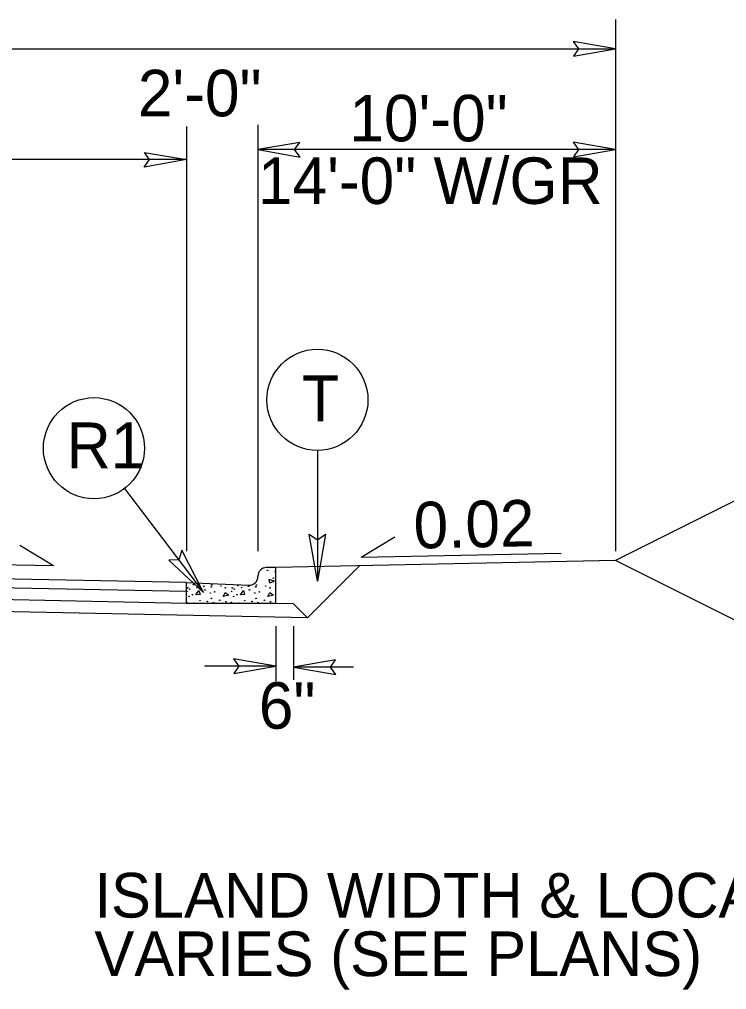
# Model space of a CAD drawing. Extents: x 1904401 to 1905163, y 193929 to 194736.
# Drawn here: x 1904998.98 to 1905018.76, y 194525.67 to 194552.8 of the extents above; entities that cross this region are included whole.
import ezdxf

# ---------------------------------------------------------------- set-up
doc = ezdxf.new("R2010")
doc.units = 0
for name, color, linetype in [('Default', 7, 'Continuous'), ('Old_Level_1', 7, 'Continuous'), ('Old_Level_11', 7, 'Continuous'), ('Old_Level_20', 7, 'Continuous'), ('Prop Dimension Text', 7, 'Continuous'), ('Prop Lane Arrow CELL', 7, 'Continuous'), ('Typical Arrow Superelevation CELL', 7, 'Continuous'), ('Typical Berm CELL', 7, 'Continuous'), ('Typical Curb CELL', 7, 'Continuous'), ('Typical Hinge Slope Arterial CELL', 7, 'Continuous'), ('Typical Pavement Slope CELL', 7, 'Continuous'), ('Typical Terminator CELL', 7, 'Continuous')]:
    doc.layers.add(name, color=color, linetype=linetype)

msp = doc.modelspace()

# ---------------------------------------------------------------- linework, layer by layer
at = {"layer": 'Default'}
msp.add_line((1905003.649, 194549.808), (1905003.649, 194537.934), dxfattribs=at)
at = {"layer": 'Old_Level_1'}
for p, q in [((1904952.149, 194551.972), (1905015.649, 194551.972)), ((1905015.649, 194549.16), (1905005.649, 194549.16)), ((1905003.649, 194548.88), (1904991.649, 194548.88))]:
    msp.add_line(p, q, dxfattribs=at)
at = {"layer": 'Old_Level_11'}
for p, q in [((1905007.314, 194540.747), (1905007.314, 194537.093)), ((1905001.92, 194539.682), (1905004.132, 194536.773))]:
    msp.add_line(p, q, dxfattribs=at)
for points in [[(1905007.54, 194538.402), (1905007.314, 194537.093), (1905007.081, 194538.409), (1905007.314, 194538.242)], [(1905003.16, 194537.679), (1905004.132, 194536.773), (1905003.521, 194537.962), (1905003.437, 194537.688)]]:
    msp.add_lwpolyline(points, close=True, dxfattribs=at)
for centre in [(1905007.314, 194542.161), (1905001.064, 194540.808)]:
    msp.add_circle(centre, 1.414, dxfattribs=at)
at = {"layer": 'Prop Dimension Text'}
for p, q in [((1905015.649, 194552.799), (1905015.649, 194537.934)), ((1905005.649, 194549.853), (1905005.649, 194537.934)), ((1905002.899, 194548.88), (1904991.899, 194548.88))]:
    msp.add_line(p, q, dxfattribs=at)
at = {"layer": 'Prop Lane Arrow CELL'}
for p, q in [((1905006.149, 194535.829), (1905006.149, 194534.291)), ((1905006.649, 194535.829), (1905006.649, 194534.331)), ((1905006.149, 194534.712), (1905004.159, 194534.712)), ((1905008.32, 194534.685), (1905006.649, 194534.685))]:
    msp.add_line(p, q, dxfattribs=at)
at = {"layer": 'Typical Arrow Superelevation CELL'}
for p, q in [((1904999.935, 194537.518), (1904998.995, 194538.086)), ((1905008.543, 194537.765), (1905009.483, 194538.333)), ((1905008.543, 194537.765), (1905014.136, 194537.876)), ((1904999.935, 194537.518), (1904994.864, 194537.619))]:
    msp.add_line(p, q, dxfattribs=at)
at = {"layer": 'Typical Berm CELL'}
msp.add_line((1905015.649, 194537.668), (1905006.149, 194537.47), dxfattribs=at)
at = {"layer": 'Typical Curb CELL'}
for p, q in [((1905006.149, 194537.47), (1905005.889, 194537.47)), ((1905006.149, 194536.47), (1905006.149, 194537.47)), ((1905003.649, 194536.47), (1905003.649, 194537.053)), ((1905003.649, 194537.053), (1905005.4, 194536.98)), ((1905005.649, 194537.22), (1905005.649, 194537.23)), ((1905005.958, 194537.137), (1905005.975, 194537.046)), ((1905006.113, 194537.092), (1905005.958, 194537.137)), ((1905005.975, 194537.046), (1905006.113, 194537.092)), ((1905003.91, 194536.71), (1905003.996, 194536.829)), ((1905004.031, 194536.716), (1905003.91, 194536.71)), ((1905003.996, 194536.829), (1905004.031, 194536.716)), ((1905004.675, 194536.659), (1905004.738, 194536.773)), ((1905004.738, 194536.773), (1905004.841, 194536.698)), ((1905005.16, 194536.71), (1905005.245, 194536.829)), ((1905005.279, 194536.716), (1905005.16, 194536.71)), ((1905005.245, 194536.829), (1905005.279, 194536.716)), ((1905005.924, 194536.659), (1905005.987, 194536.773)), ((1905005.987, 194536.773), (1905006.09, 194536.698)), ((1905006.149, 194536.47), (1905003.649, 194536.47)), ((1905004.841, 194536.698), (1905004.675, 194536.659)), ((1905006.09, 194536.698), (1905005.924, 194536.659))]:
    msp.add_line(p, q, dxfattribs=at)
for centre in [(1905005.919, 194537.394), (1905006.136, 194537.36), (1905003.848, 194536.995), (1905003.99, 194537.012), (1905004.361, 194536.983), (1905005.61, 194536.983), (1905006.084, 194537.177), (1905003.666, 194536.807), (1905003.683, 194536.904), (1905003.739, 194536.87), (1905003.819, 194536.71), (1905003.945, 194536.91), (1905004.139, 194536.949), (1905004.167, 194536.847), (1905004.316, 194536.761), (1905004.344, 194536.933), (1905004.441, 194536.79), (1905004.618, 194536.955), (1905004.738, 194536.904), (1905004.915, 194536.807), (1905004.932, 194536.904), (1905004.988, 194536.87), (1905005.068, 194536.71), (1905005.097, 194536.964), (1905005.194, 194536.91), (1905005.388, 194536.949), (1905005.416, 194536.847), (1905005.565, 194536.761), (1905005.593, 194536.933), (1905005.69, 194536.79), (1905005.867, 194536.955), (1905005.987, 194536.904), (1905003.66, 194536.499), (1905003.723, 194536.664), (1905003.871, 194536.476), (1905004.03, 194536.545), (1905004.236, 194536.522), (1905004.35, 194536.607), (1905004.407, 194536.493), (1905004.584, 194536.556), (1905004.755, 194536.516), (1905004.909, 194536.499), (1905004.972, 194536.664), (1905005.12, 194536.476), (1905005.279, 194536.545), (1905005.485, 194536.522), (1905005.599, 194536.607), (1905005.656, 194536.493), (1905005.833, 194536.556), (1905006.004, 194536.516)]:
    msp.add_circle(centre, 0.00802, dxfattribs=at)
for centre, start, end in [((1905005.889, 194537.23), 90, 180), ((1905005.41, 194537.22), 267.6155, 0)]:
    msp.add_arc(centre, 0.24, start, end, dxfattribs=at)
at = {"layer": 'Typical Hinge Slope Arterial CELL'}
for p in [(1905028.169, 194543.928), (1905028.102, 194531.442)]:
    msp.add_line(p, (1905015.649, 194537.668), dxfattribs=at)
at = {"layer": 'Typical Pavement Slope CELL'}
for p, q in [((1905003.649, 194537.053), (1904991.899, 194537.288)), ((1905007.04, 194536.069), (1905008.49, 194537.519)), ((1905003.649, 194536.803), (1904991.894, 194537.038)), ((1905007.04, 194536.069), (1904983.899, 194536.532)), ((1905003.649, 194536.47), (1904991.888, 194536.705)), ((1905006.649, 194536.46), (1905006.149, 194536.47)), ((1905007.04, 194536.069), (1905006.649, 194536.46))]:
    msp.add_line(p, q, dxfattribs=at)
at = {"layer": 'Typical Terminator CELL'}
for points in [[(1905014.478, 194551.77), (1905015.649, 194551.972), (1905014.471, 194552.18), (1905014.621, 194551.972)], [(1905006.821, 194549.361), (1905005.649, 194549.16), (1905006.828, 194548.951), (1905006.678, 194549.16)], [(1905014.478, 194548.958), (1905015.649, 194549.16), (1905014.471, 194549.368), (1905014.621, 194549.16)], [(1905002.478, 194549.081), (1905003.649, 194548.88), (1905002.471, 194548.671), (1905002.621, 194548.88)], [(1905004.977, 194534.511), (1905006.149, 194534.712), (1905004.971, 194534.921), (1905005.121, 194534.712)], [(1905007.821, 194534.887), (1905006.649, 194534.685), (1905007.827, 194534.477), (1905007.677, 194534.685)]]:
    msp.add_lwpolyline(points, close=True, dxfattribs=at)

# ---------------------------------------------------------------- texts
at = {"layer": 'Old_Level_1'}
for s, p in [('2\'-0"', (1905002.292, 194550.09)), ('10\'-0" ', (1905008.21, 194549.389)), ('14\'-0" W/GR', (1905005.652, 194547.639))]:
    msp.add_text(s, height=1.3, dxfattribs=at).set_placement(p)
at = {"layer": 'Old_Level_20'}
for s, height, p in [('T', 1.279, (1905006.878, 194541.564)), ('R1', 1.2792, (1905000.299, 194540.249))]:
    msp.add_text(s, height=height, dxfattribs=at).set_placement(p)
at = {"layer": 'Prop Dimension Text'}
msp.add_text('0.02', height=1.3, rotation=1.1462, dxfattribs=at).set_placement((1905010.017, 194538.002))
at = {"layer": 'Prop Lane Arrow CELL'}
msp.add_text('6"', height=1.3, rotation=0.0002, dxfattribs=at).set_placement((1905005.677, 194532.965))
for s, p in [('ISLAND WIDTH & LOCATION', (1905001.077, 194527.684)), ('VARIES (SEE PLANS)', (1905001.077, 194526.046))]:
    msp.add_text(s, height=1.25, dxfattribs=at).set_placement(p)

doc.saveas('drawing.dxf')
